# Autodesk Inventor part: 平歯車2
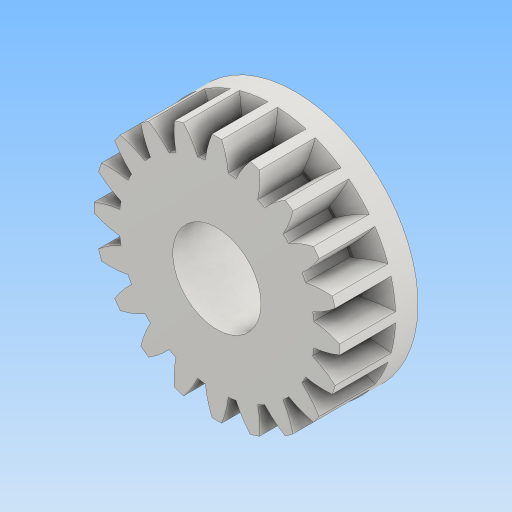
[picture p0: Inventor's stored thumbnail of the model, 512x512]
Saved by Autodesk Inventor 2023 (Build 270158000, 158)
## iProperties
CustomPartVersion: 1
Created: 2024-01
Part Number: 平歯車2
Material: Steel
Document SubType Name: Modeling
Designer: kumagai
Categories: <?xml version="1.0" encoding="UTF-16"?> <MemberInstance><Categories><FamilyTemplate><FamilyTemplateParameter ValueType="xs:double" Id="1" ObjectReferenceKey="da
Density: 1 g/cm^3
Appearance: Steel
Author: kumagai
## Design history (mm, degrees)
sketch "Sketch1"
  geometry: C1 r 11 at (0, 0)
  constraints: 1 centre point
  dimensions: "d0" = 22 diameter of C1 (= da_da)
extrude "Extrusion1" new body sketch "Sketch1" distance "d1" = 5 (= da_b); taper "d2" = 0 deg
workplane "Work Plane2"
sketch "Sketch2"
  geometry: C1 r 11 at (0, 0) reference; C2 r 10 at (0, 0)
  constraints: 1 centre point, 1 coincident
  dimensions: "d3" = 20 diameter of C2 (= da_d)
feature "ピッチ円直径" sketch "Sketch2" dims "d4" = 10, "d5" = 0
workplane "Work Plane8"
workplane "Work Plane9"
feature "平歯車" dims "da_b" = 5, "da_d" = 20 (= 0.1 x da_z), "da_aw" = 56, "da_da" = 22 (computed from da_d), "da_df" = 17.5 (computed from da_d), "da_dw" = 20 (= da_d), angle "da_beta" = 0 deg, "da_lefttooth" = 0, "da_righttooth" = 0
sketch "スケッチ3"
  geometry: C1 r 3.95 at (0, 0); 1 further point
  constraints: 1 centre point, 1 coincident
  dimensions: "d49" = 7.9 diameter of C1
sketch "スケッチ4"
  geometry: L1 (0, 10)-(0, -4) reference; L2 (-2.2, 0)-(13.2, 0) reference; L3 (0, 1)-(9, 1); L4 (9, 1)-(11, 0); L5 (11, 0)-(0, 0); L6 (0, 0)-(0, 1); L7 (11, 0)-(11, -2); L8 (11, -2)-(0, -2); L9 (0, -2)-(0, 0); L10 (10.992, 0)-(11, 0) reference; 2 further points
  constraints: 14 end point, 4 point on line, 1 vertical
  dimensions: "d57" = 1 distance between parallel lines of L3 L2; "d58" = 2 distance between parallel lines of L5 L8; "d61" = 2 distance from line of L7 L3.end
revolve "回転1" sketch "スケッチ4" stored, may be unused: angle "d54" = 360 deg
extrude "押し出し2" cut sketch "スケッチ3" extent not by distance; stored distance "d55" = 0; taper "d56" = 0 deg
body "Solid1"
body "Srf1"
other parameters: "d16" = 56 (= da_aw), "d17" = 0, "d34" = 9 deg (computed from da_z), "d39" = 0, "d41" = 0, "d43" = 56 (= da_aw), "d46" = 56 (= da_aw), "d47" = 0, "d48" = 0
